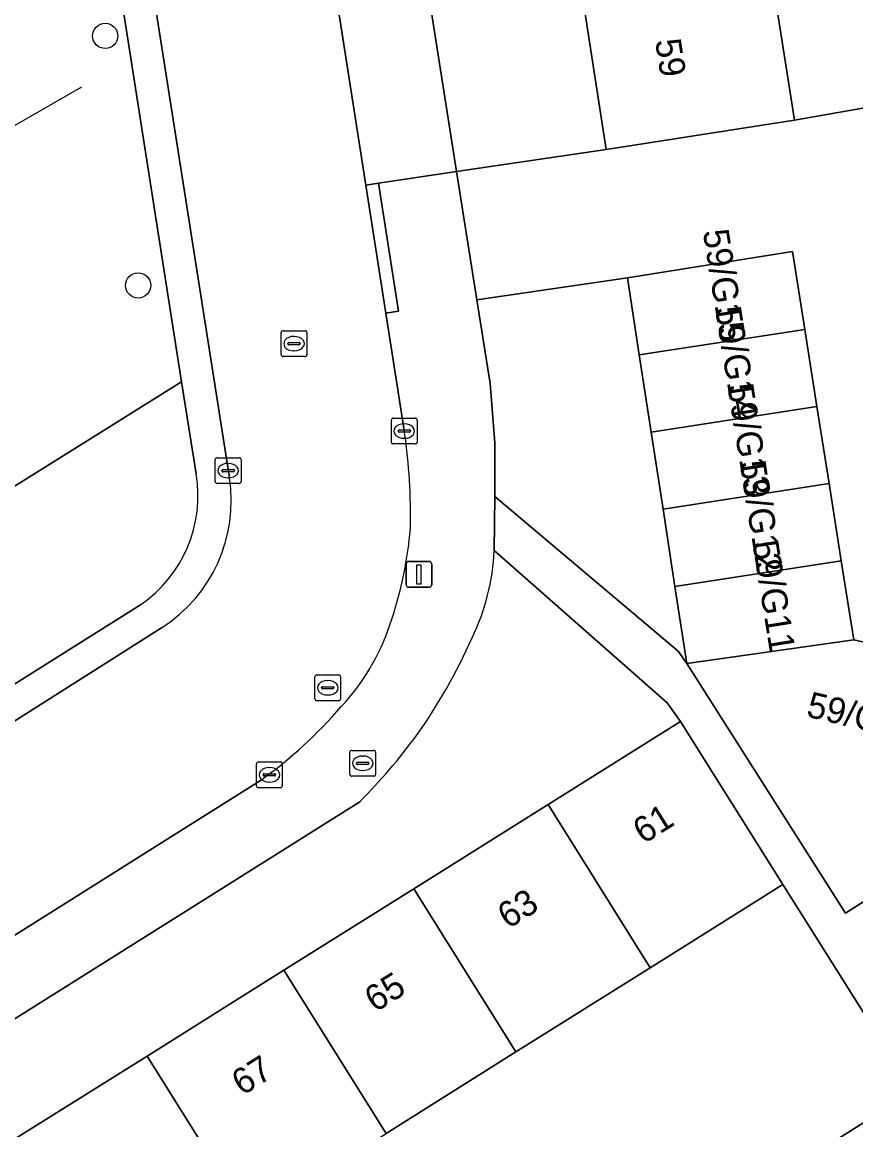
# Model space of a CAD drawing. Extents: x 160077 to 160948, y 386481 to 387498.
# Drawn here: x 160283.4 to 160315.74, y 387143.58 to 387186.53 of the extents above; entities that cross this region are included whole.
import ezdxf

# ---------------------------------------------------------------- set-up
doc = ezdxf.new("R2010")
doc.units = 0
for name, color, linetype in [('IMGEO_Boom', 7, 'Continuous'), ('IMGEO_Brandkraan', 7, 'Continuous'), ('IMGEO_Erf', 7, 'Continuous'), ('IMGEO_Groenvoorziening', 7, 'Continuous'), ('IMGEO_Hek', 7, 'Continuous'), ('IMGEO_Kolk', 7, 'Continuous'), ('IMGEO_Lichtmast', 7, 'Continuous'), ('IMGEO_Pand', 7, 'Continuous'), ('IMGEO_Pand_nummerreeks', 7, 'Continuous'), ('IMGEO_Rijbaan_lokaal_open', 7, 'Continuous'), ('IMGEO_Rioolput', 7, 'Continuous'), ('IMGEO_Voetpad_open', 7, 'Continuous')]:
    doc.layers.add(name, color=color, linetype=linetype)

msp = doc.modelspace()

# ---------------------------------------------------------------- linework, layer by layer
at = {"layer": 'IMGEO_Boom'}
for centre in [(160286.623, 387185.992), (160287.898, 387176.321)]:
    msp.add_circle(centre, 0.489, dxfattribs=at)
at = {"layer": 'IMGEO_Brandkraan'}
for p, q in [((160296.11, 387157.369), (160296.11, 387158.221)), ((160296.185, 387158.295), (160297.037, 387158.295)), ((160296.598, 387158.075), (160296.623, 387158.075)), ((160297.111, 387158.221), (160297.111, 387157.369)), ((160296.369, 387157.789), (160296.369, 387157.801)), ((160296.807, 387157.752), (160296.409, 387157.752)), ((160296.412, 387157.838), (160296.81, 387157.838)), ((160296.853, 387157.801), (160296.853, 387157.789)), ((160297.037, 387157.295), (160296.185, 387157.295)), ((160296.621, 387157.515), (160296.596, 387157.515))]:
    msp.add_line(p, q, dxfattribs=at)
for points in [[(160296.11, 387157.369), (160296.11, 387158.221)], [(160296.185, 387158.295), (160297.037, 387158.295)], [(160297.111, 387158.221), (160297.111, 387157.369)], [(160297.037, 387157.295), (160296.185, 387157.295)]]:
    msp.add_lwpolyline(points, dxfattribs=at)
for centre, radius, start, end in [((160296.187, 387158.219), 0.0765, 91.552, 178.448), ((160296.187, 387158.219), 0.0765, 91.552, 178.448), ((160297.035, 387158.219), 0.0765, 1.552, 88.448), ((160297.035, 387158.219), 0.0765, 1.552, 88.448), ((160296.409, 387157.798), 0.0403, 85.8775, 175.7526), ((160296.406, 387157.788), 0.0366, 178.938, 274.7102), ((160296.81, 387157.795), 0.043, 264.8664, 352.4533), ((160296.814, 387157.8), 0.0386, 1.7309, 96.639), ((160296.187, 387157.371), 0.0765, 181.552, 268.448), ((160296.187, 387157.371), 0.0765, 181.552, 268.448), ((160297.035, 387157.371), 0.0765, 271.552, 358.448), ((160297.035, 387157.371), 0.0765, 271.552, 358.448)]:
    msp.add_arc(centre, radius, start, end, dxfattribs=at)
for centre, major_axis, ratio, start_param, end_param in [((160296.597, 387157.795), (-0.387, 0.002), 0.722429, 4.712389, 7.853982), ((160296.622, 387157.795), (-0.39, 0.002), 0.717154, 1.570796, 4.712389)]:
    msp.add_ellipse(centre, major_axis=major_axis, ratio=ratio, start_param=start_param, end_param=end_param, dxfattribs=at)
at = {"layer": 'IMGEO_Erf'}
for points in [[(160294.39, 387217.959), (160300.247, 387180.732), (160306.058, 387181.585), (160305.155, 387187.353)], [(160312.452, 387188.495), (160313.355, 387182.727), (160328.071, 387185.305), (160327.763, 387187.064)], [(160288.249, 387146.446), (160293.555, 387149.771), (160298.589, 387152.926), (160303.802, 387156.194), (160308.942, 387159.415), (160308.416, 387160.138), (160301.708, 387166.041)], [(160296.499, 387156.3), (160255.281, 387130.409), (160257.386, 387127.102), (160262.53, 387130.326), (160267.734, 387133.588), (160272.723, 387136.714), (160278.049, 387140.052), (160283.079, 387143.205), (160288.249, 387146.446)], [(160319.242, 387143.043), (160312.905, 387153.093), (160307.765, 387149.871), (160302.552, 387146.604), (160297.518, 387143.449)], [(160312.804, 387141.83), (160316.456, 387144.133), (160317.74, 387142.096)]]:
    msp.add_lwpolyline(points, dxfattribs=at)
msp.add_lwpolyline([(160307.798, 387170.634), (160307.337, 387173.624), (160306.876, 387176.614), (160301.035, 387175.756), (160301.557, 387172.514), (160301.729, 387170.222), (160301.732, 387168.133), (160308.841, 387162.146), (160309.181, 387161.663), (160308.72, 387164.653), (160308.259, 387167.643)], close=True, dxfattribs=at)
for centre, radius, start, end in [((160293.219, 387166.386), 8.496, 333.9977, 357.6747), ((160280.251, 387171.847), 22.559, 324.8711, 335.9713), ((160277.86, 387174.523), 26.067, 315.6469, 323.0843)]:
    msp.add_arc(centre, radius, start, end, dxfattribs=at)
at = {"layer": 'IMGEO_Groenvoorziening'}
msp.add_lwpolyline([(160256.205, 387205.545), (160276.052, 387174.158), (160280.595, 387166.974), (160289.587, 387172.582), (160282.17, 387219.786), (160278.038, 387219.161), (160267.814, 387212.785), (160259.261, 387207.451)], close=True, dxfattribs=at)
for points in [[(160290.147, 387169.017), (160289.587, 387172.582), (160280.595, 387166.974), (160276.052, 387174.158), (160256.205, 387205.545)], [(160277.657, 387157.447), (160287.987, 387163.943)]]:
    msp.add_lwpolyline(points, dxfattribs=at)
msp.add_arc((160285.127, 387168.157), 5.093, 304.1624, 9.7187, dxfattribs=at)
at = {"layer": 'IMGEO_Hek'}
msp.add_lwpolyline([(160285.7, 387184), (160276.867, 387178.939)], dxfattribs=at)
at = {"layer": 'IMGEO_Kolk'}
for p, q in [((160297.723, 387170.248), (160297.723, 387171.1)), ((160297.798, 387171.174), (160298.65, 387171.174)), ((160298.211, 387170.954), (160298.236, 387170.954)), ((160298.724, 387171.1), (160298.724, 387170.248)), ((160297.982, 387170.668), (160297.982, 387170.68)), ((160298.42, 387170.631), (160298.022, 387170.631)), ((160298.025, 387170.717), (160298.423, 387170.717)), ((160298.466, 387170.68), (160298.466, 387170.668)), ((160298.65, 387170.174), (160297.798, 387170.174)), ((160298.234, 387170.394), (160298.209, 387170.394)), ((160290.893, 387168.714), (160290.893, 387169.566)), ((160290.968, 387169.64), (160291.82, 387169.64)), ((160291.381, 387169.42), (160291.406, 387169.42)), ((160291.894, 387169.566), (160291.894, 387168.714)), ((160291.152, 387169.134), (160291.152, 387169.146)), ((160291.59, 387169.097), (160291.192, 387169.097)), ((160291.195, 387169.183), (160291.593, 387169.183)), ((160291.404, 387168.86), (160291.379, 387168.86)), ((160291.636, 387169.146), (160291.636, 387169.134)), ((160291.82, 387168.64), (160290.968, 387168.64)), ((160292.49, 387156.922), (160292.49, 387157.774)), ((160292.565, 387157.848), (160293.417, 387157.848)), ((160293.491, 387157.774), (160293.491, 387156.922)), ((160292.749, 387157.342), (160292.749, 387157.354)), ((160293.187, 387157.305), (160292.789, 387157.305)), ((160292.792, 387157.391), (160293.19, 387157.391)), ((160292.978, 387157.628), (160293.003, 387157.628)), ((160293.233, 387157.354), (160293.233, 387157.342)), ((160293.417, 387156.848), (160292.565, 387156.848)), ((160293.001, 387157.068), (160292.976, 387157.068))]:
    msp.add_line(p, q, dxfattribs=at)
for points in [[(160297.723, 387170.248), (160297.723, 387171.1)], [(160297.798, 387171.174), (160298.65, 387171.174)], [(160298.724, 387171.1), (160298.724, 387170.248)], [(160298.65, 387170.174), (160297.798, 387170.174)], [(160290.893, 387168.714), (160290.893, 387169.566)], [(160290.968, 387169.64), (160291.82, 387169.64)], [(160291.894, 387169.566), (160291.894, 387168.714)], [(160291.82, 387168.64), (160290.968, 387168.64)], [(160292.49, 387156.922), (160292.49, 387157.774)], [(160292.565, 387157.848), (160293.417, 387157.848)], [(160293.491, 387157.774), (160293.491, 387156.922)], [(160293.417, 387156.848), (160292.565, 387156.848)]]:
    msp.add_lwpolyline(points, dxfattribs=at)
for centre, radius, start, end in [((160297.8, 387171.098), 0.0765, 91.552, 178.448), ((160297.8, 387171.098), 0.0765, 91.552, 178.448), ((160298.648, 387171.098), 0.0765, 1.552, 88.448), ((160298.648, 387171.098), 0.0765, 1.552, 88.448), ((160298.022, 387170.677), 0.0403, 85.8775, 175.7526), ((160298.019, 387170.667), 0.0366, 178.938, 274.7102), ((160298.423, 387170.674), 0.043, 264.8664, 352.4533), ((160298.427, 387170.679), 0.0386, 1.7309, 96.639), ((160297.8, 387170.25), 0.0765, 181.552, 268.448), ((160297.8, 387170.25), 0.0765, 181.552, 268.448), ((160298.648, 387170.25), 0.0765, 271.552, 358.448), ((160298.648, 387170.25), 0.0765, 271.552, 358.448), ((160290.97, 387169.564), 0.0765, 91.552, 178.448), ((160290.97, 387169.564), 0.0765, 91.552, 178.448), ((160291.818, 387169.564), 0.0765, 1.552, 88.448), ((160291.818, 387169.564), 0.0765, 1.552, 88.448), ((160291.192, 387169.143), 0.0403, 85.8775, 175.7526), ((160291.189, 387169.133), 0.0366, 178.938, 274.7102), ((160291.593, 387169.14), 0.043, 264.8664, 352.4533), ((160291.597, 387169.145), 0.0386, 1.7309, 96.639), ((160290.97, 387168.716), 0.0765, 181.552, 268.448), ((160290.97, 387168.716), 0.0765, 181.552, 268.448), ((160291.818, 387168.716), 0.0765, 271.552, 358.448), ((160291.818, 387168.716), 0.0765, 271.552, 358.448), ((160292.567, 387157.772), 0.0765, 91.552, 178.448), ((160292.567, 387157.772), 0.0765, 91.552, 178.448), ((160293.415, 387157.772), 0.0765, 1.552, 88.448), ((160293.415, 387157.772), 0.0765, 1.552, 88.448), ((160292.789, 387157.351), 0.0403, 85.8775, 175.7526), ((160292.786, 387157.341), 0.0366, 178.938, 274.7102), ((160293.19, 387157.348), 0.043, 264.8664, 352.4533), ((160293.194, 387157.353), 0.0386, 1.7309, 96.639), ((160292.567, 387156.924), 0.0765, 181.552, 268.448), ((160292.567, 387156.924), 0.0765, 181.552, 268.448), ((160293.415, 387156.924), 0.0765, 271.552, 358.448), ((160293.415, 387156.924), 0.0765, 271.552, 358.448)]:
    msp.add_arc(centre, radius, start, end, dxfattribs=at)
for centre, major_axis, ratio, start_param, end_param in [((160298.21, 387170.674), (-0.387, 0.002), 0.722429, 4.712389, 7.853982), ((160298.235, 387170.674), (-0.39, 0.002), 0.717154, 1.570796, 4.712389), ((160291.38, 387169.14), (-0.387, 0.002), 0.722429, 4.712389, 7.853982), ((160291.405, 387169.14), (-0.39, 0.002), 0.717154, 1.570796, 4.712389), ((160292.977, 387157.348), (-0.387, 0.002), 0.722429, 4.712389, 7.853982), ((160293.002, 387157.348), (-0.39, 0.002), 0.717154, 1.570796, 4.712389)]:
    msp.add_ellipse(centre, major_axis=major_axis, ratio=ratio, start_param=start_param, end_param=end_param, dxfattribs=at)
at = {"layer": 'IMGEO_Lichtmast'}
for p, q in [((160298.295, 387164.719), (160298.295, 387165.519)), ((160298.295, 387165.519), (160298.295, 387164.719)), ((160298.395, 387165.619), (160299.185, 387165.619)), ((160299.185, 387165.619), (160298.395, 387165.619)), ((160299.285, 387165.519), (160299.285, 387164.719)), ((160299.285, 387164.719), (160299.285, 387165.519)), ((160299.185, 387164.619), (160298.395, 387164.619)), ((160298.395, 387164.619), (160299.185, 387164.619))]:
    msp.add_line(p, q, dxfattribs=at)
msp.add_lwpolyline([(160298.715, 387165.494), (160298.865, 387165.494), (160298.865, 387164.744), (160298.715, 387164.744), (160298.715, 387165.494)], dxfattribs=at)
for centre, start, end in [((160298.395, 387165.519), 90, 180), ((160298.395, 387165.519), 90, 180), ((160299.185, 387165.519), 0, 90), ((160299.185, 387165.519), 360, 90), ((160298.395, 387164.719), 180, 270), ((160298.395, 387164.719), 180, 270), ((160299.185, 387164.719), 270, 0), ((160299.185, 387164.719), 270, 0)]:
    msp.add_arc(centre, 0.1, start, end, dxfattribs=at)
at = {"layer": 'IMGEO_Pand'}
for points in [[(160305.155, 387187.353), (160306.058, 387181.585), (160313.355, 387182.727), (160312.452, 387188.495)], [(160313.285, 387177.633), (160306.876, 387176.614), (160307.337, 387173.624), (160313.76, 387174.614)], [(160307.337, 387173.624), (160307.798, 387170.634), (160314.23, 387171.625), (160313.76, 387174.614)], [(160314.7, 387168.636), (160314.23, 387171.625), (160307.798, 387170.634), (160308.259, 387167.643)], [(160308.259, 387167.643), (160308.72, 387164.653), (160315.171, 387165.648), (160314.7, 387168.636)], [(160315.654, 387162.575), (160315.171, 387165.648), (160308.72, 387164.653), (160309.181, 387161.663)], [(160309.181, 387161.663), (160315.34, 387151.978), (160322.409, 387156.492), (160319.017, 387161.827), (160315.654, 387162.575)], [(160307.765, 387149.871), (160312.905, 387153.093), (160311.598, 387155.179), (160308.942, 387159.415), (160303.802, 387156.194)], [(160302.552, 387146.604), (160307.765, 387149.871), (160303.802, 387156.194), (160298.589, 387152.926)], [(160298.589, 387152.926), (160293.555, 387149.771), (160297.518, 387143.449), (160302.552, 387146.604)], [(160292.212, 387140.123), (160297.518, 387143.449), (160293.555, 387149.771), (160288.249, 387146.446)], [(160287.042, 387136.883), (160292.212, 387140.123), (160288.249, 387146.446), (160283.079, 387143.205)], [(160317.74, 387142.096), (160316.456, 387144.133), (160312.804, 387141.83), (160314.083, 387139.79)]]:
    msp.add_lwpolyline(points, close=True, dxfattribs=at)
at = {"layer": 'IMGEO_Rijbaan_lokaal_open'}
for points in [[(160296.731, 387180.213), (160295.282, 387189.473), (160292.311, 387208.1), (160285.447, 387207.006), (160291.439, 387168.858)], [(160298.232, 387170.614), (160297.509, 387175.239), (160296.731, 387180.213)], [(160288.806, 387163.046), (160278.216, 387156.343), (160281.95, 387150.406), (160292.647, 387157.133)]]:
    msp.add_lwpolyline(points, dxfattribs=at)
msp.add_lwpolyline([(160330.678, 387180.264), (160328.383, 387183.872), (160328.071, 387185.305), (160313.355, 387182.727), (160306.058, 387181.585), (160300.247, 387180.732), (160301.035, 387175.756), (160306.876, 387176.614), (160313.285, 387177.633), (160313.76, 387174.614), (160314.23, 387171.625), (160314.7, 387168.636), (160315.171, 387165.648), (160315.654, 387162.575), (160319.017, 387161.827), (160321.543, 387163.433), (160324.07, 387165.04), (160326.596, 387166.646), (160329.122, 387168.252), (160331.649, 387169.859), (160334.175, 387171.465), (160332.509, 387174.085), (160330.842, 387176.706), (160329.176, 387179.326)], close=True, dxfattribs=at)
for centre, radius, start, end in [((160276.203, 387167.399), 22.263, 358.737, 8.304), ((160285.696, 387167.957), 5.813, 302.3416, 8.9146), ((160283.269, 387168.181), 15.244, 340.7623, 355.211), ((160289.463, 387165.897), 8.645, 316.951, 341.5274), ((160282.386, 387171.508), 17.661, 305.5208, 319.3227)]:
    msp.add_arc(centre, radius, start, end, dxfattribs=at)
at = {"layer": 'IMGEO_Rioolput'}
for p, q in [((160293.445, 387173.638), (160293.445, 387174.49)), ((160293.52, 387174.564), (160294.372, 387174.564)), ((160294.446, 387174.49), (160294.446, 387173.638)), ((160293.704, 387174.058), (160293.704, 387174.07)), ((160294.142, 387174.021), (160293.744, 387174.021)), ((160293.747, 387174.107), (160294.145, 387174.107)), ((160293.933, 387174.344), (160293.958, 387174.344)), ((160294.188, 387174.07), (160294.188, 387174.058)), ((160294.372, 387173.564), (160293.52, 387173.564)), ((160293.956, 387173.784), (160293.931, 387173.784)), ((160294.753, 387160.296), (160294.753, 387161.148)), ((160294.828, 387161.222), (160295.68, 387161.222)), ((160295.754, 387161.148), (160295.754, 387160.296)), ((160295.012, 387160.716), (160295.012, 387160.728)), ((160295.45, 387160.679), (160295.052, 387160.679)), ((160295.055, 387160.765), (160295.453, 387160.765)), ((160295.241, 387161.002), (160295.266, 387161.002)), ((160295.496, 387160.728), (160295.496, 387160.716)), ((160295.68, 387160.222), (160294.828, 387160.222)), ((160295.264, 387160.442), (160295.239, 387160.442))]:
    msp.add_line(p, q, dxfattribs=at)
for points in [[(160293.445, 387173.638), (160293.445, 387174.49)], [(160293.52, 387174.564), (160294.372, 387174.564)], [(160294.446, 387174.49), (160294.446, 387173.638)], [(160294.372, 387173.564), (160293.52, 387173.564)], [(160294.753, 387160.296), (160294.753, 387161.148)], [(160294.828, 387161.222), (160295.68, 387161.222)], [(160295.754, 387161.148), (160295.754, 387160.296)], [(160295.68, 387160.222), (160294.828, 387160.222)]]:
    msp.add_lwpolyline(points, dxfattribs=at)
for centre, radius, start, end in [((160293.522, 387174.488), 0.0765, 91.552, 178.448), ((160293.522, 387174.488), 0.0765, 91.552, 178.448), ((160294.37, 387174.488), 0.0765, 1.552, 88.448), ((160294.37, 387174.488), 0.0765, 1.552, 88.448), ((160293.744, 387174.067), 0.0403, 85.8775, 175.7526), ((160293.741, 387174.057), 0.0366, 178.938, 274.7102), ((160294.145, 387174.064), 0.043, 264.8664, 352.4533), ((160294.149, 387174.069), 0.0386, 1.7309, 96.639), ((160293.522, 387173.64), 0.0765, 181.552, 268.448), ((160293.522, 387173.64), 0.0765, 181.552, 268.448), ((160294.37, 387173.64), 0.0765, 271.552, 358.448), ((160294.37, 387173.64), 0.0765, 271.552, 358.448), ((160294.83, 387161.146), 0.0765, 91.552, 178.448), ((160294.83, 387161.146), 0.0765, 91.552, 178.448), ((160295.678, 387161.146), 0.0765, 1.552, 88.448), ((160295.678, 387161.146), 0.0765, 1.552, 88.448), ((160295.052, 387160.725), 0.0403, 85.8775, 175.7526), ((160295.049, 387160.715), 0.0366, 178.938, 274.7102), ((160295.453, 387160.722), 0.043, 264.8664, 352.4533), ((160295.457, 387160.727), 0.0386, 1.7309, 96.639), ((160294.83, 387160.298), 0.0765, 181.552, 268.448), ((160294.83, 387160.298), 0.0765, 181.552, 268.448), ((160295.678, 387160.298), 0.0765, 271.552, 358.448), ((160295.678, 387160.298), 0.0765, 271.552, 358.448)]:
    msp.add_arc(centre, radius, start, end, dxfattribs=at)
for centre, major_axis, ratio, start_param, end_param in [((160293.932, 387174.064), (-0.387, 0.002), 0.722429, 4.712389, 7.853982), ((160293.957, 387174.064), (-0.39, 0.002), 0.717154, 1.570796, 4.712389), ((160295.24, 387160.722), (-0.387, 0.002), 0.722429, 4.712389, 7.853982), ((160295.265, 387160.722), (-0.39, 0.002), 0.717154, 1.570796, 4.712389)]:
    msp.add_ellipse(centre, major_axis=major_axis, ratio=ratio, start_param=start_param, end_param=end_param, dxfattribs=at)
at = {"layer": 'IMGEO_Voetpad_open'}
for points in [[(160291.439, 387168.858), (160285.447, 387207.006), (160285.014, 387209.762), (160279.601, 387244.335)], [(160278.407, 387243.737), (160281.04, 387226.98), (160281.656, 387223.056), (160282.17, 387219.786), (160289.587, 387172.582), (160290.147, 387169.017)], [(160290.814, 387217.485), (160291.872, 387210.855), (160292.311, 387208.1), (160295.282, 387189.473), (160296.731, 387180.213), (160297.224, 387180.29), (160300.247, 387180.732), (160294.39, 387217.959)], [(160301.708, 387166.041), (160301.732, 387168.133), (160301.729, 387170.222), (160301.557, 387172.514), (160301.035, 387175.756), (160300.247, 387180.732), (160297.224, 387180.29), (160298.002, 387175.316), (160297.509, 387175.239), (160298.232, 387170.614)], [(160336.058, 387141.786), (160334.228, 387144.737), (160325.437, 387158.426), (160324.932, 387158.103), (160322.409, 387156.492), (160315.34, 387151.978), (160309.181, 387161.663), (160308.841, 387162.146), (160301.732, 387168.133), (160301.708, 387166.041), (160308.416, 387160.138), (160308.942, 387159.415), (160311.598, 387155.179), (160312.905, 387153.093), (160319.242, 387143.043)], [(160287.987, 387163.943), (160277.657, 387157.447)], [(160278.216, 387156.343), (160288.806, 387163.046)], [(160292.647, 387157.133), (160281.95, 387150.406), (160272.691, 387144.583), (160266.781, 387140.866), (160264.195, 387139.299), (160246.804, 387128.394), (160245.754, 387127.736), (160241.091, 387124.7), (160236.718, 387121.973), (160238.871, 387120.28), (160242.235, 387122.407), (160246.937, 387125.176), (160250.939, 387127.668), (160255.281, 387130.409), (160296.499, 387156.3)]]:
    msp.add_lwpolyline(points, dxfattribs=at)
msp.add_lwpolyline([(160297.509, 387175.239), (160298.002, 387175.316), (160297.224, 387180.29), (160296.731, 387180.213)], close=True, dxfattribs=at)
for centre, radius, start, end in [((160276.203, 387167.399), 22.263, 358.737, 8.304), ((160285.127, 387168.157), 5.093, 304.1624, 9.7187), ((160285.696, 387167.957), 5.813, 302.3416, 8.9146), ((160283.269, 387168.181), 15.244, 340.7623, 355.211), ((160293.219, 387166.386), 8.496, 333.9977, 357.6747), ((160289.463, 387165.897), 8.645, 316.951, 341.5274), ((160280.251, 387171.847), 22.559, 324.8711, 335.9713), ((160282.386, 387171.508), 17.661, 305.5208, 319.3227), ((160277.86, 387174.523), 26.067, 315.6469, 323.0843)]:
    msp.add_arc(centre, radius, start, end, dxfattribs=at)

# ---------------------------------------------------------------- texts
at = {"layer": 'IMGEO_Pand_nummerreeks'}
for s, rotation, p in [('59', 278.896, (160307.946, 387185.812)), ('59/G15', 279.0524, (160309.801, 387178.424)), ('59/G14', 279.0524, (160310.277, 387175.435)), ('59/G13', 279.0524, (160310.754, 387172.445)), ('59/G12', 279.0524, (160311.229, 387169.462)), ('59/G11', 279.0524, (160311.724, 387166.357)), ('59/G10', 346.866, (160313.779, 387159.611)), ('61', 32.0777, (160307.501, 387154.642)), ('63', 32.0777, (160302.251, 387151.351)), ('65', 32.0777, (160297.095, 387148.119)), ('67', 32.0777, (160291.939, 387144.888))]:
    msp.add_text(s, height=1, rotation=rotation, dxfattribs=at).set_placement(p)

doc.saveas('drawing.dxf')
